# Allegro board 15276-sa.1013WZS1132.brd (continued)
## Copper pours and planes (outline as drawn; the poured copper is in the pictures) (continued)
USB30_VCCC on L4: 22.97,42.17 22.97,38.75 23.6,38.11 23.6,37.09 23.48,36.97 21.32,36.97 20.3,37.98 20.3,46.49 17.76,49.03 17.76,51.7 20.3,54.24 20.3,56.4 20.81,56.91 20.81,60.84 20.17,61.48 18.52,61.48 18.14,61.86 18.14,64.4 18.52,64.78 23.86,64.78 24.11,64.53 24.11,56.65 24.1,56.64 24.1,55.24 23.73,54.87 23.73,42.94

Small or netless copper shapes (teardrops, artwork), in the pictures only: 29 on L2VCC, 29 on L5GND, 1 on TOP

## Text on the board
Ref Des/Silkscreen Bottom: F5201:1.1A/24V | F5203:1.1A/24V | X1902:48MHZ | X601:32.768KHZ | F6201:.5A/6V | SPK1 | HDD1 | FAN1 | DIMM A | ONL Y DDR3L | DIMM B
Ref Des/Silkscreen Top: F5501:1.1A/6V | X3001:25MHZ | DCN1 | M2L3 | ODD1 | PWR1 | TPAD1 | LCD1 | KB1 | I0 | 15276-SA | IRIS BEEMA MB | 448.08702.00SA | MADE IN TAIWAN
User.27: GND | APU_VDD | 1D35V_S3 | APU_VDDNB | 0D95V_S0 | AUD_AGND | 3D3V_S0 | 3D3V_WLAN_S0
User.28: 1D35V_S3 | AUD_AGND | GND
User.30: ByImpedance:100.0@_REF_L1=("4.0/6.0(L1)" "3.5/5.0(L1)" "5.0/11.0(L1)")|_REF_L6=("4.0/6.0(L6)" "3.5/5.0(L6)" "5.0/11.0(L6)")|Type="DP"|_REF_L4=("4.0/9.0(L4)" "3.5/7.0(L4)")|_REF_L3=("4.0/9.0(L3)" "3.5/7.0(L3)")|imp="100.0" | ByImpedance:110.0@_REF_L1=("4.0/12.0(L1)")|_REF_L6=("4.0/12.0(L6)")|Type="DP"|_REF_L4=("3.5/13.0(L4)")|_REF_L3=("3.5/13.0(L3)")|imp="110.0" | ByImpedance:33.0@_REF_L1=("12.0(L1)")|_REF_L6=("12.0(L6)")|Type="SE"|_REF_L4=("12.5(L4)")|_REF_L3=("12.5(L3)")|imp="33.0" | ByImpedance:35.0@_REF_L1=("11.0(L1)")|_REF_L6=("11.0(L6)")|Type="SE"|_REF_L4=("10.5(L4)")|_REF_L3=("10.5(L3)")|imp="35.0" | ByImpedance:37.5@_REF_L1=("10.0(L1)")|_REF_L6=("10.0(L6)")|Type="SE"|_REF_L4=("9.5(L4)")|_REF_L3=("9.5(L3)")|imp="37.5" | ByImpedance:40.0@_REF_L1=("8.5(L1)")|_REF_L6=("8.5(L6)")|Type="SE"|_REF_L4=("8.0(L4)")|_REF_L3=("8.0(L3)")|imp="40.0" | ByImpedance:45.0@_REF_L1=("7.0(L1)")|_REF_L6=("7.0(L6)")|Type="SE"|_REF_L4=("6.5(L4)")|_REF_L3=("6.5(L3)")|imp="45.0" | ByImpedance:48.0@_REF_L1=("6.0(L1)")|_REF_L6=("6.0(L6)")|Type="SE"|_REF_L4=("5.5(L4)")|_REF_L3=("5.5(L3)")|imp="48.0" | ByImpedance:50.0@_REF_L1=("5.5(L1)" "5.5(L1)")|_REF_L6=("5.5(L6)" "5.5(L6)")|Type="SE"|_REF_L4=("5.0(L4)")|_REF_L3=("5.0(L3)")|imp="50.0" | ByImpedance:52.0@_REF_L1=("5.0(L1)")|_REF_L6=("5.0(L6)")|Type="SE"|_REF_L4=("4.5(L4)")|_REF_L3=("4.5(L3)")|imp="52.0" | ByImpedance:55.0@_REF_L1=("4.5(L1)")|_REF_L6=("4.5(L6)")|Type="SE"|_REF_L4=("4.0(L4)")|_REF_L3=("4.0(L3)")|imp="55.0" | ByImpedance:60.0@_REF_L1=("3.5(L1)")|_REF_L6=("3.5(L6)")|Type="SE"|_REF_L4=("nil(L4)")|_REF_L3=("nil(L3)")|imp="60.0" | ByImpedance:65.0@_REF_L1=("10.0/5.0(L1)")|_REF_L6=("10.0/5.0(L6)")|Type="DP"|_REF_L4=("9.0/5.0(L4)")|_REF_L3=("9.0/5.0(L3)")|imp="65.0" | ByImpedance:70.0@_REF_L1=("8.5/5.0(L1)")|_REF_L6=("8.5/5.0(L6)")|Type="DP"|_REF_L4=("8.0/5.0(L4)")|_REF_L3=("8.0/5.0(L3)")|imp="70.0" | ByImpedance:72.0@_REF_L1=("8.0/5.0(L1)")|_REF_L6=("8.0/5.0(L6)")|Type="DP"|_REF_L4=("7.0/5.0(L4)")|_REF_L3=("7.0/5.0(L3)")|imp="72.0" | ByImpedance:75.0@_REF_L1=("7.0/4.5(L1)")|_REF_L6=("7.0/4.5(L6)")|Type="DP"|_REF_L4=("7.0/6.0(L4)")|_REF_L3=("7.0/6.0(L3)")|imp="75.0" | ByImpedance:80.0@_REF_L1=("6.0/4.5(L1)")|_REF_L6=("6.0/4.5(L6)")|Type="DP"|_REF_L4=("5.5/5.0(L4)" "6.0/6.0(L4)" "5.0/4.0(L4)")|_REF_L3=("5.5/5.0(L3)" "6.0/6.0(L3)" "5.0/4.0(L3)")|imp="80.0" | ByImpedance:83.0@_REF_L1=("5.0/4.0(L1)")|_REF_L6=("5.0/4.0(L6)")|Type="DP"|_REF_L4=("4.5/4.0(L4)")|_REF_L3=("4.5/4.0(L3)")|imp="83.0" | ByImpedance:85.0@_REF_L1=("5.5/5.0(L1)" "5.0/4.5(L1)" "6.0/6.0(L1)")|_REF_L6=("5.5/5.0(L6)" "5.0/4.5(L6)" "6.0/6.0(L6)")|Type="DP"|_REF_L4=("5.5/7.0(L4)" "5.0/5.5(L4)" "4.5/4.5(L4)")|_REF_L3=("5.5/7.0(L3)" "5.0/5.5(L3)" "4.5/4.5(L3)")|imp="85.0" | ByImpedance:88.0@_REF_L1=("5.0/5.0(L1)" "4.5/4.0(L1)")|_REF_L6=("5.0/5.0(L6)" "4.5/4.0(L6)")|Type="DP"|_REF_L4=("4.0/4.5(L4)" "5.0/7.0(L4)")|_REF_L3=("4.0/4.5(L3)" "5.0/7.0(L3)")|imp="88.0" | ByImpedance:90.0@_REF_L1=("4.0/4.0(L1)" "5.0/6.0(L1)")|_REF_L6=("4.0/4.0(L6)" "5.0/6.0(L6)")|Type="DP"|_REF_L4=("5.0/8.0(L4)" "4.0/5.0(L4)" "4.5/6.0(L4)")|_REF_L3=("5.0/8.0(L3)" "4.0/5.0(L3)" "4.5/6.0(L3)")|imp="90.0" | ByImpedance:93.0@_REF_L1=("4.0/4.5(L1)" "5.0/6.5(L1)")|_REF_L6=("4.0/4.5(L6)" "5.0/6.5(L6)")|Type="DP"|_REF_L4=("4.0/6.0(L4)")|_REF_L3=("4.0/6.0(L3)")|imp="93.0" | ByImpedance:95.0@_REF_L1=("4.5/6.0(L1)")|_REF_L6=("4.5/6.0(L6)")|Type="DP"|_REF_L4=("4.0/6.5(L4)")|_REF_L3=("4.0/6.5(L3)")|imp="95.0" | LayerIndex:nil | Source:6-1.2-3k.xls | artWorks:("_REF_L3" "_REF_L4" "_REF_L6" "_REF_L1") | gtImpOutlineUsed:BOARD GEOMETRY/PANEL_OUTLINE
User.31: Board Accuracy Check,Oct 09 13:21:20 2015,Passed | Dummy-Static-No Shape On Layer Check,Oct 09 13:21:20 2015,Passed | Split Plane Check,Oct 04 19:50:36 2015,Passed
User.33: This gerber is just for your reference to find the DP impedance traces in layer L1. | DP IMPEDANCE TABLE: L1 | * - Denotes that this Impedance | is NOT used | IMP(Ohm) | *65.0 | *70.0 | *72.0 | *75.0 | *80.0 | *83.0 | 85.0 | *85.0 | *88.0 | 90.0 | *90.0 | *93.0 | *95.0 | *100.0 | 100.0 | *110.0 | WIDTH(mils) | 10.0/5.0 | 8.5/5.0 | 8.0/5.0 | 7.0/4.5 | 6.0/4.5 | 5.0/4.0 | 5.5/5.0 | 5.0/4.5 | 6.0/6.0 | 5.0/5.0 | 4.5/4.0 | 4.0/4.0 | 5.0/6.0 | 4.0/4.5 | 5.0/6.5 | 4.5/6.0 | 4.0/6.0 | 3.5/5.0 | 5.0/11.0 | 4.0/12.0 | TYPE | DP
User.35: This gerber is just for your reference to find the SE impedance traces in layer L1. | SE IMPEDANCE TABLE: L1 | * - Denotes that this Impedance | is NOT used | IMP(Ohm) | *33.0 | *35.0 | *37.5 | 40.0 | *45.0 | *48.0 | 50.0 | *52.0 | 55.0 | *60.0 | WIDTH(mils) | 12.0 | 11.0 | 10.0 | 8.5 | 7.0 | 6.0 | 5.5 | 5.0 | 4.5 | 3.5 | TYPE | SE
User.37: This gerber is just for your reference to find the DP impedance traces in layer L3. | DP IMPEDANCE TABLE: L3 | * - Denotes that this Impedance | is NOT used | IMP(Ohm) | *65.0 | *70.0 | 72.0 | *75.0 | *80.0 | *83.0 | *85.0 | *88.0 | *90.0 | 90.0 | *93.0 | *95.0 | *100.0 | *110.0 | WIDTH(mils) | 9.0/5.0 | 8.0/5.0 | 7.0/5.0 | 7.0/6.0 | 5.5/5.0 | 6.0/6.0 | 5.0/4.0 | 4.5/4.0 | 5.5/7.0 | 5.0/5.5 | 4.5/4.5 | 4.0/4.5 | 5.0/7.0 | 5.0/8.0 | 4.0/5.0 | 4.5/6.0 | 4.0/6.0 | 4.0/6.5 | 4.0/9.0 | 3.5/7.0 | 3.5/13.0 | TYPE | DP
User.39: This gerber is just for your reference to find the SE impedance traces in layer L3. | SE IMPEDANCE TABLE: L3 | * - Denotes that this Impedance | is NOT used | IMP(Ohm) | *33.0 | *35.0 | *37.5 | 40.0 | *45.0 | *48.0 | *50.0 | *52.0 | 55.0 | *60.0 | WIDTH(mils) | 12.5 | 10.5 | 9.5 | 8.0 | 6.5 | 5.5 | 5.0 | 4.5 | 4.0 | nil | TYPE | SE
User.41: This gerber is just for your reference to find the DP impedance traces in layer L4. | DP IMPEDANCE TABLE: L4 | * - Denotes that this Impedance | is NOT used | IMP(Ohm) | *65.0 | *70.0 | *72.0 | *75.0 | *80.0 | 80.0 | *83.0 | *85.0 | 85.0 | *88.0 | *90.0 | 90.0 | *93.0 | *95.0 | *100.0 | *110.0 | WIDTH(mils) | 9.0/5.0 | 8.0/5.0 | 7.0/5.0 | 7.0/6.0 | 5.5/5.0 | 6.0/6.0 | 5.0/4.0 | 4.5/4.0 | 5.5/7.0 | 5.0/5.5 | 4.5/4.5 | 4.0/4.5 | 5.0/7.0 | 5.0/8.0 | 4.0/5.0 | 4.5/6.0 | 4.0/6.0 | 4.0/6.5 | 4.0/9.0 | 3.5/7.0 | 3.5/13.0 | TYPE | DP
User.43: This gerber is just for your reference to find the SE impedance traces in layer L4. | SE IMPEDANCE TABLE: L4 | * - Denotes that this Impedance | is NOT used | IMP(Ohm) | *33.0 | *35.0 | *37.5 | 40.0 | *45.0 | *48.0 | 50.0 | *52.0 | 55.0 | *60.0 | WIDTH(mils) | 12.5 | 10.5 | 9.5 | 8.0 | 6.5 | 5.5 | 5.0 | 4.5 | 4.0 | nil | TYPE | SE
User.45: Note:Refer to DRILL layer for ELLIPSE drill direction | FIGURE | SIZE | 10.0 | 16.0 | 20.0 | 24.0 | 28.0 | 36.0 | 48.0 | 115.0 | 126.0 | 166.0 | 182.0 | 44.0 | 46.0 | 52.0 | 56.0 | 63.0 | 65.0 | 86.0 | 158.0 | 60.0x36.0 | 67.0x36.0 | 71.0x36.0 | 90.0x28.0 | 95.0x28.0 | 95.0x36.0 | 110.0x40.0 | 130.0x24.0 | 150.0x119.0 | DRILL CHART: TOP to BOTTOM | ALL UNITS ARE IN MILS | PLATED | NON-PLATED | QTY | 2725 | 678 | 19 | 15 | 9 | 8 | 4 | 1 | 3 | 2 | 6 | This gerber is just for your reference to find the DP impedance traces in layer L6. | This gerber is just for your reference to find the SE impedance traces in layer L6. | DP IMPEDANCE TABLE: L6 | SE IMPEDANCE TABLE: L6 | * - Denotes that this Impedance | is NOT used | Model | IRIS BEEMA MB | PCB_NO | 15276 | VER. | SA | Layer | DRILL | L1 | L2VCC | L3 | TMASK | TPLACE | TSILK | TSMD | Designer | STEFAN | Date | 10/09/2015 | IMP(Ohm) | *33.0 | *65.0 | *35.0 | *70.0 | *37.5 | 72.0 | *75.0 | 40.0 | *45.0 | 80.0 | *48.0 | *83.0 | 50.0 | 85.0 | *85.0 | *52.0 | *88.0 | 55.0 | *60.0 | 90.0 | *90.0 | *93.0 | *95.0 | *100.0 | 100.0 | *110.0 | WIDTH(mils) | 12.0 | 11.0 | 8.5 | 7.0 | 6.0 | 5.5 | 5.0 | 4.5 | 3.5 | 10.0/5.0 | 8.5/5.0 | 8.0/5.0 | 7.0/4.5 | 6.0/4.5 | 5.0/4.0 | 5.5/5.0 | 5.0/4.5 | 6.0/6.0 | 5.0/5.0 | 4.5/4.0 | 4.0/4.0 | 5.0/6.0 | 4.0/4.5 | 5.0/6.5 | 4.5/6.0 | 4.0/6.0 | 3.5/5.0 | 5.0/11.0 | 4.0/12.0 | TYPE | SE | DP | BMASK | BPLACE | BSILK | BSMD | L4 | L5GND | L6
